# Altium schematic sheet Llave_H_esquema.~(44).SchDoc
size A4
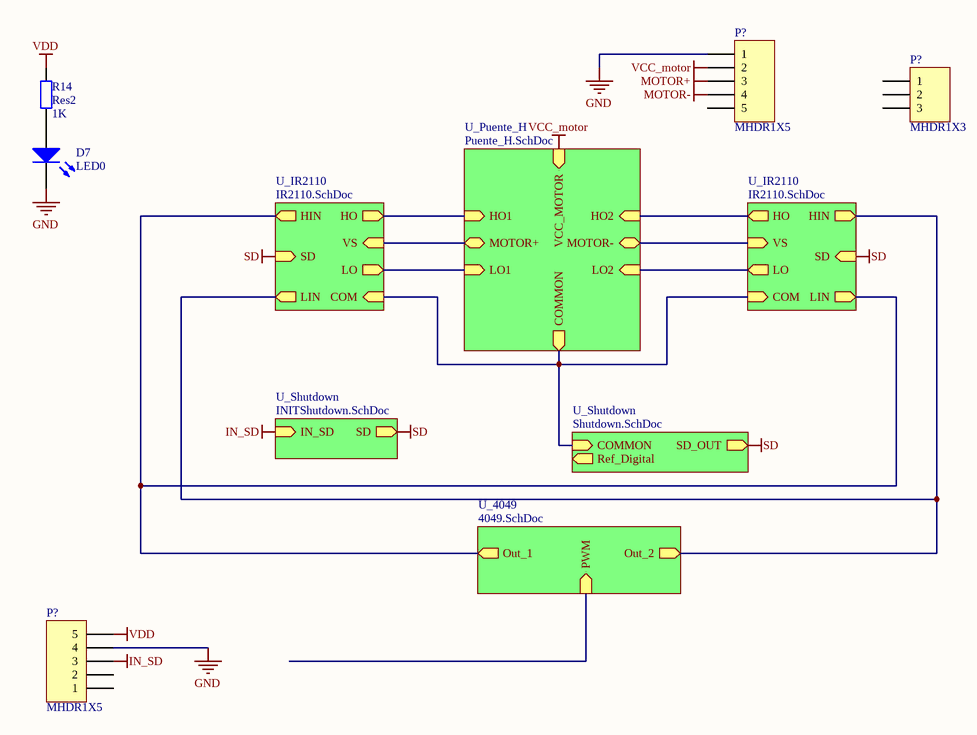
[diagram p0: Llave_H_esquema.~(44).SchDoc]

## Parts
(Parts that share a designator on the sheet are numbered #1, #2 ... from top to bottom, then left to right.)
D7  LED0  [LED-0]
P?#1  MHDR1X5  [MHDR1X5]
P?#2  MHDR1X3  [MHDR1X3]
P?#3  MHDR1X5  [MHDR1X5]
R14  Res2  value 1K  [AXIAL-0.4]

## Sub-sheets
U_4049 = 4049.SchDoc: PWM (in), Out_1 (out), Out_2 (out)
U_IR2110 = IR2110.SchDoc: SD (in), HIN (out), LIN (out), HO (out), LO (out), VS (in), COM (in)
U_IR2110 = IR2110.SchDoc: SD (in), HIN (out), LIN (out), HO (out), LO (out), VS (in), COM (in)
U_Puente_H = Puente_H.SchDoc: HO1 (in), LO1 (in), HO2 (in), LO2 (in), MOTOR+ (bidir), MOTOR- (bidir), VCC_MOTOR (in), COMMON (out)
U_Shutdown = INITShutdown.SchDoc: IN_SD (in), SD (out)
U_Shutdown = Shutdown.SchDoc: COMMON (in), SD_OUT (out), Ref_Digital (out)

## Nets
GND: D7.2(K) P?#1.1 P?#3.4
IN_SD: P?#3.3 ; sheet U_Shutdown/IN_SD
MOTOR+: P?#1.3
MOTOR-: P?#1.4
SD: sheet U_IR2110/SD, sheet U_IR2110/SD, sheet U_Shutdown/SD, sheet U_Shutdown/SD_OUT
VCC_motor: P?#1.2 ; sheet U_Puente_H/VCC_MOTOR
VDD: P?#3.5 R14.2
NetD7_1: D7.1(A) R14.1
(unnamed): sheet U_IR2110/HIN, sheet U_IR2110/LIN, sheet U_4049/Out_1
(unnamed): sheet U_IR2110/LIN, sheet U_IR2110/HIN, sheet U_4049/Out_2  [a separate net that carries the same name]
(unnamed): sheet U_IR2110/HO, sheet U_Puente_H/HO1  [a separate net that carries the same name]
(unnamed): sheet U_IR2110/LO, sheet U_Puente_H/LO1  [a separate net that carries the same name]
(unnamed): sheet U_IR2110/VS, sheet U_Puente_H/MOTOR+  [a separate net that carries the same name]
(unnamed): sheet U_IR2110/COM, sheet U_IR2110/COM, sheet U_Puente_H/COMMON, sheet U_Shutdown/COMMON  [a separate net that carries the same name]
(unnamed): sheet U_IR2110/HO, sheet U_Puente_H/HO2  [a separate net that carries the same name]
(unnamed): sheet U_IR2110/LO, sheet U_Puente_H/LO2  [a separate net that carries the same name]
(unnamed): sheet U_IR2110/VS, sheet U_Puente_H/MOTOR-  [a separate net that carries the same name]

Not connected (* = marked no-connect by the designer): P?#1 5; P?#2 1 2 3; P?#3 1 2

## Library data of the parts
D7 = LED0: Typical INFRARED GaAs LED
P?#1 P?#3 = MHDR1X5: Header, 5-Pin
P?#2 = MHDR1X3: Header, 3-Pin
R14 = Res2: Resistor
